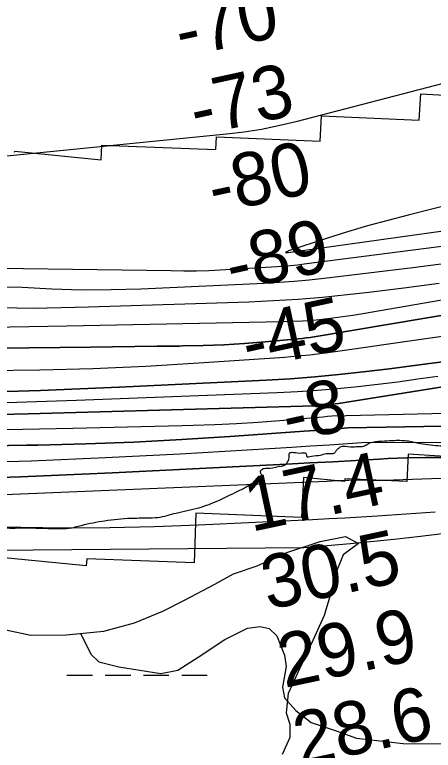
# Model space of a CAD drawing. Extents: x 3297772 to 3335630, y 634068 to 659439.
# Drawn here: x 3327309 to 3327833, y 645151 to 646073 of the extents above; entities that cross this region are included whole.
import ezdxf

# ---------------------------------------------------------------- set-up
doc = ezdxf.new("R2010")
doc.units = 0
for name, color, linetype in [('V-RIVR-EDGE', 7, 'Continuous'), ('V-RIVR-RANG', 7, 'Continuous'), ('V-RRAP-RVMT', 7, 'Continuous'), ('V-SITE-VEGE', 7, 'Continuous'), ('V-TOPO-DPTH', 7, 'Continuous'), ('V-TOPO-MAJR', 7, 'Continuous'), ('V-TOPO-MINR', 7, 'Continuous'), ('V-TOPO-WATR', 7, 'Continuous'), ('V-WETL-SWMP', 7, 'Continuous')]:
    doc.layers.add(name, color=color, linetype=linetype)

msp = doc.modelspace()

# ---------------------------------------------------------------- linework, layer by layer
at = {"layer": 'V-RIVR-EDGE'}
msp.add_spline([(3325196.76, 645366.57), (3325219.07, 645371.99), (3325232.62, 645380.37), (3325238.11, 645381.45), (3325244.69, 645381.43), (3325256.03, 645384.7), (3325270.28, 645383.93), (3325278.69, 645383.91), (3325292.94, 645383.87), (3325303.18, 645385.68), (3325337.93, 645393.27), (3325341.96, 645396.18), (3325345.26, 645400.19), (3325350.02, 645402.74), (3325363.55, 645407.09), (3325383.3, 645410.34), (3325403.77, 645410.65), (3325424.61, 645412.06), (3325447.65, 645414.56), (3325474.71, 645418.52), (3325488.24, 645421.04), (3325503.6, 645423.2), (3325524.43, 645423.51), (3325540.88, 645421.28), (3325546.37, 645422.36), (3325555.87, 645423.43), (3325573.43, 645427.41), (3325598.29, 645430.64), (3325642.54, 645437.11), (3325676.18, 645439.95), (3325709.08, 645440.6), (3325736.86, 645438.7), (3325745.63, 645439.05), (3325778.18, 645445.91), (3325790.25, 645447.71), (3325816.2, 645448.01), (3325841.42, 645446.85), (3325861.17, 645447.9), (3325877.99, 645450.78), (3325891.88, 645451.48), (3325905.04, 645450.72), (3325915.64, 645449.96), (3325925.51, 645449.94), (3325931.73, 645453.58), (3325946.36, 645457.2), (3325975.98, 645462.24), (3326020.59, 645466.52), (3326051.66, 645467.17), (3326078.35, 645468.93), (3326092.26, 645474.75), (3326108.35, 645477.63), (3326121.15, 645479.43), (3326134.67, 645479.39), (3326146.37, 645479), (3326156.98, 645483.73), (3326173.06, 645481.86), (3326186.58, 645479.63), (3326209.25, 645482.5), (3326231.92, 645484.27), (3326245.82, 645486.8), (3326251.3, 645487.51), (3326255.69, 645487.5), (3326266.65, 645484.55), (3326272.13, 645484.9), (3326286.76, 645485.6), (3326304.31, 645487.02), (3326331.71, 645482.93), (3326352.19, 645483.24), (3326375.22, 645483.92), (3326399.71, 645484.95), (3326430.42, 645487.07), (3326472.11, 645494.64), (3326504.66, 645500.78), (3326533.19, 645508.02), (3326555.14, 645512.72), (3326569.77, 645515.24), (3326590.6, 645516.28), (3326611.44, 645516.96), (3326626.07, 645517.29), (3326648.74, 645520.16), (3326682.73, 645518.61), (3326701.37, 645519.67), (3326720.39, 645522.91), (3326726.24, 645522.89), (3326745.6, 645516.63), (3326754.37, 645517.71), (3326767.18, 645522.43), (3326775.22, 645522.41), (3326789.47, 645520.91), (3326806.64, 645515.75), (3326817.97, 645513.16), (3326835.51, 645512.75), (3326847.57, 645511.63), (3326853.78, 645509.42), (3326864.75, 645508.29), (3326886.31, 645508.61), (3326901.66, 645506.01), (3326929.42, 645497.17), (3326947.69, 645495.3), (3326969.62, 645490.49), (3326983.5, 645489.36), (3327007.99, 645487.47), (3327024.79, 645482.31), (3327048.53, 645473.84), (3327083.59, 645460.96), (3327102.59, 645457.26), (3327123.05, 645450.63), (3327142.04, 645445.1), (3327153.38, 645445.8), (3327176.02, 645437.34), (3327197.58, 645434.36), (3327219.15, 645434.31), (3327235.22, 645431.71), (3327254.59, 645429.83), (3327257.15, 645427.63), (3327254.58, 645423.62), (3327249.09, 645419.98), (3327247.62, 645417.42), (3327250.17, 645413.76), (3327256.38, 645412.65), (3327262.23, 645412.63), (3327269.91, 645413.71), (3327273.57, 645415.53), (3327277.23, 645418.81), (3327282.37, 645427.57), (3327290.05, 645429.75), (3327306.5, 645429.71), (3327316.74, 645430.05), (3327337.57, 645429.63), (3327362.43, 645429.2), (3327376.69, 645429.53), (3327392.41, 645433.15), (3327421.31, 645438.93), (3327454.21, 645442.13), (3327473.95, 645442.45), (3327488.21, 645443.15), (3327510.89, 645448.57), (3327539.05, 645455.08), (3327565.4, 645464.89), (3327591.75, 645477.62), (3327596.87, 645480.16), (3327603.46, 645484.17), (3327608.95, 645487.08), (3327619.57, 645492.9), (3327619.57, 645494.37), (3327617.02, 645498.39), (3327616.66, 645500.59), (3327617.4, 645502.05), (3327621.42, 645504.6), (3327628.37, 645504.94), (3327642.63, 645507.47), (3327647.02, 645508.55), (3327651.79, 645514.39), (3327652.52, 645515.85), (3327653.64, 645524.26), (3327655.1, 645524.62), (3327658.03, 645524.61), (3327668.26, 645523.85), (3327673.01, 645523.84), (3327674.11, 645522.74), (3327674.47, 645519.82), (3327680.68, 645519.8), (3327691.65, 645521.24), (3327699.33, 645523.05), (3327707.74, 645523.39), (3327709.93, 645524.12), (3327712.14, 645527.4), (3327715.43, 645530.32), (3327716.9, 645531.41), (3327729.69, 645531.38), (3327739.2, 645532.09), (3327745.78, 645532.44), (3327750.9, 645534.98), (3327757.12, 645537.53), (3327772.48, 645538.95), (3327784.91, 645539.65), (3327802.45, 645538.88), (3327817.07, 645535.91), (3327829.86, 645534.06), (3327842.28, 645532.93), (3327856.91, 645533.26), (3327866.41, 645534.33), (3327870.44, 645536.51), (3327879.22, 645537.22), (3327886.16, 645537.57), (3327892.01, 645538.65), (3327898.23, 645538.64), (3327904.08, 645538.62), (3327915.77, 645534.94), (3327925.63, 645534.55), (3327947.21, 645537.06), (3327969.14, 645537.73), (3327991.81, 645538.04), (3328022.88, 645537.6), (3328037.49, 645535.74), (3328060.16, 645536.04), (3328088.31, 645536.34), (3328117.55, 645537.37), (3328121.94, 645535.89), (3328132.53, 645533.67), (3328150.81, 645535.09), (3328167.63, 645534.32), (3328186.64, 645536.83), (3328199.44, 645540.09), (3328214.44, 645541.88), (3328232.35, 645542.93), (3328250.99, 645542.15), (3328289.37, 645541.69), (3328309.85, 645543.84), (3328325.21, 645547.82), (3328337.3, 645556.56), (3328349.76, 645568.96), (3328357.82, 645579.54), (3328362.59, 645586.47), (3328365.52, 645587.93), (3328369.54, 645588.28), (3328387.82, 645586.41), (3328406.82, 645583.07), (3328410.84, 645583.06), (3328415.59, 645584.15), (3328422.17, 645584.13), (3328433.86, 645580.81), (3328450.66, 645574.56), (3328468.55, 645563.91), (3328480.23, 645556.57), (3328490.82, 645555.09), (3328505.81, 645553.22), (3328518.95, 645546.97), (3328533.19, 645539.99), (3328537.57, 645539.25), (3328541.23, 645539.97), (3328548.17, 645537.4), (3328551.82, 645534.1), (3328555.84, 645532.63), (3328561.68, 645532.25), (3328569.73, 645533.69), (3328596.79, 645537.64), (3328623.85, 645539.77), (3328643.95, 645540.45), (3328661.5, 645541.87), (3328682.34, 645542.18), (3328707.93, 645541.39), (3328751.8, 645544.94), (3328776.29, 645544.14), (3328800.41, 645542.99), (3328822.34, 645540.74), (3328852.31, 645540.3), (3328872.42, 645539.52), (3328885.21, 645538.03), (3328904.21, 645535.05), (3328911.52, 645534.67), (3328920.29, 645534.65), (3328935.65, 645535.34), (3328949.9, 645535.67), (3328970.74, 645535.26), (3328996.69, 645533), (3329015.69, 645532.22), (3329030.32, 645534.01), (3329055.19, 645539.07), (3329082.26, 645548.5), (3329110.8, 645559.4), (3329140.81, 645572.85), (3329150.69, 645574.29), (3329156.53, 645572.81), (3329161.99, 645564.03), (3329167.83, 645559.26), (3329176.96, 645555.22), (3329189.39, 645555.19), (3329198.9, 645558.09), (3329204.02, 645560.27), (3329207.32, 645563.91), (3329210.26, 645571.22), (3329213.2, 645575.96), (3329221.99, 645583.25), (3329230.78, 645588.35), (3329243.95, 645594.9), (3329264.07, 645601.43), (3329299.92, 645609.38), (3329325.51, 645612.24), (3329356.22, 645614.36), (3329383.65, 645617.58), (3329433.01, 645624.4), (3329465.56, 645631.27), (3329478.74, 645637.45), (3329492.65, 645643.26), (3329501.79, 645643.97), (3329512.02, 645644.68), (3329517.87, 645644.66), (3329517.87, 645642.84), (3329522.24, 645637.71), (3329527.36, 645636.6), (3329531.01, 645636.95), (3329539.79, 645639.13), (3329550.03, 645641.66), (3329558.44, 645641.64), (3329571.59, 645637.95), (3329581.45, 645634.27), (3329594.96, 645629.49), (3329608.46, 645619.22), (3329621.6, 645611.14), (3329628.55, 645610.03), (3329633.3, 645610.38), (3329647.95, 645620.58), (3329662.22, 645626.03), (3329671.72, 645627.1), (3329687.81, 645626.33), (3329707.91, 645624.82), (3329744.09, 645622.54), (3329761.64, 645621.76), (3329766.75, 645621.02), (3329774.06, 645620.64), (3329779.18, 645621.35), (3329786.85, 645618.41), (3329792.32, 645614.74), (3329809.5, 645610.68), (3329840.92, 645606.94)], degree=3, dxfattribs=at)
at = {"layer": 'V-RRAP-RVMT'}
for p, q in [((3327815.69, 645941.15), (3327817.77, 645974.23)), ((3327817.77, 645974.23), (3327958.55, 645966.13)), ((3327691.81, 645914.84), (3327693.27, 645946.56)), ((3327693.27, 645946.56), (3327815.69, 645941.15)), ((3327560.7, 645904.5), (3327561.43, 645920.37)), ((3327561.43, 645920.37), (3327691.81, 645914.84)), ((3327417.01, 645891.44), (3327417.81, 645909.69)), ((3327417.81, 645909.69), (3327560.7, 645904.5)), ((3327308.52, 645900.8), (3327308.64, 645902.05)), ((3327308.64, 645902.05), (3327417.01, 645891.44)), ((3327801.82, 645522.17), (3327800.2, 645487.91)), ((3327937.16, 645514.4), (3327801.82, 645522.17)), ((3327670.59, 645493.31), (3327668.41, 645443.07)), ((3327722, 645487.96), (3327670.59, 645493.31)), ((3327722.36, 645491.41), (3327722, 645487.96)), ((3327800.2, 645487.91), (3327722.36, 645491.41)), ((3327535.85, 645448.6), (3327533.66, 645386.07)), ((3327668.41, 645443.07), (3327535.85, 645448.6)), ((3327398.03, 645382.52), (3327259.58, 645395.96)), ((3327398.88, 645391.03), (3327398.03, 645382.52)), ((3327533.66, 645386.07), (3327398.88, 645391.03))]:
    msp.add_line(p, q, dxfattribs=at)
at = {"layer": 'V-SITE-VEGE'}
msp.add_lwpolyline([(3327297.44, 645302.08), (3327328.77, 645295.47), (3327373.27, 645295.8), (3327420.48, 645300.39), (3327458.8, 645310.8), (3327494.41, 645325.46), (3327521.52, 645339.35), (3327559.46, 645359.43), (3327583.08, 645372.17), (3327612.49, 645382.58), (3327649.66, 645399.18), (3327691.46, 645413.06), (3327723.2, 645419.22), (3327739.5, 645410.57), (3327720.43, 645396.26), (3327710.9, 645372.41), (3327708.51, 645355.71), (3327703.74, 645343.78), (3327696.59, 645319.93), (3327682.29, 645288.92), (3327665.6, 645253.15), (3327651.3, 645222.14), (3327648.91, 645198.29), (3327653.68, 645183.98), (3327653.68, 645167.28), (3327644.15, 645145.81)], dxfattribs=at)
at = {"layer": 'V-TOPO-DPTH'}
for points in [[(3328198.59, 645755.91), (3327684.12, 645669.54), (3327679.13, 645668.76), (3327674.14, 645668.06), (3327669.13, 645667.48), (3327664.11, 645666.97), (3327622.45, 645663.25), (3327596.57, 645661.25), (3327570.68, 645659.64), (3327544.75, 645658.62), (3327518.81, 645658.01), (3327514.96, 645657.96), (3327487.08, 645657.63), (3327459.2, 645657.3), (3327431.32, 645656.97), (3327403.44, 645656.64), (3327210.13, 645654.4), (3327104.28, 645653.12), (3326998.43, 645651.75), (3326892.58, 645650.28), (3326786.73, 645648.72), (3326647.86, 645646.61)], [(3328198.59, 645755.91), (3327684.12, 645669.54), (3327679.13, 645668.76), (3327674.14, 645668.06), (3327669.13, 645667.48), (3327664.11, 645666.97), (3327622.45, 645663.25), (3327596.57, 645661.25), (3327570.68, 645659.64), (3327544.75, 645658.62), (3327518.81, 645658.01), (3327514.96, 645657.96), (3327487.08, 645657.63), (3327459.2, 645657.3), (3327431.32, 645656.97), (3327403.44, 645656.64), (3327210.13, 645654.4), (3327104.28, 645653.12), (3326998.43, 645651.75), (3326892.58, 645650.28), (3326786.73, 645648.72), (3326647.86, 645646.61)], [(3326717.66, 645622.15), (3326787.87, 645623.57), (3326858.09, 645624.73), (3326928.31, 645625.5), (3326998.54, 645626.01), (3327007.12, 645626.05), (3327073.69, 645626.34), (3327140.25, 645626.63), (3327206.82, 645626.9), (3327273.39, 645627.16), (3327339.93, 645628.06), (3327406.44, 645629.83), (3327472.91, 645632.88), (3327539.34, 645636.79), (3327646.77, 645644.16), (3327662.76, 645645.44), (3327678.73, 645646.96), (3327694.65, 645648.84), (3327710.55, 645650.96), (3327929.11, 645682.62)], [(3326717.66, 645622.15), (3326787.87, 645623.57), (3326858.09, 645624.73), (3326928.31, 645625.5), (3326998.54, 645626.01), (3327007.12, 645626.05), (3327073.69, 645626.34), (3327140.25, 645626.63), (3327206.82, 645626.9), (3327273.39, 645627.16), (3327339.93, 645628.06), (3327406.44, 645629.83), (3327472.91, 645632.88), (3327539.34, 645636.79), (3327646.77, 645644.16), (3327662.76, 645645.44), (3327678.73, 645646.96), (3327694.65, 645648.84), (3327710.55, 645650.96), (3327929.11, 645682.62)], [(3328279.42, 645676.32), (3327714.71, 645586), (3327711, 645585.44), (3327707.28, 645584.93), (3327703.55, 645584.48), (3327699.82, 645584.08), (3327696.08, 645583.75), (3327692.34, 645583.47), (3327688.59, 645583.27), (3327684.84, 645583.13), (3327325.61, 645572.79), (3327201.58, 645569.87), (3327077.54, 645567.81), (3326953.48, 645567.05), (3326829.41, 645567.16), (3326609.21, 645568.5)], [(3326609.21, 645568.5), (3326829.41, 645567.16), (3326953.48, 645567.05), (3327077.54, 645567.81), (3327201.58, 645569.87), (3327325.61, 645572.79), (3327684.84, 645583.13), (3327688.59, 645583.27), (3327692.34, 645583.47), (3327696.08, 645583.75), (3327699.82, 645584.08), (3327703.55, 645584.48), (3327707.28, 645584.93), (3327711, 645585.44), (3327714.71, 645586), (3328279.42, 645676.32)], [(3326750.06, 645598.6), (3326782.39, 645598.64), (3326814.71, 645598.55), (3326847.04, 645598.45), (3326879.36, 645598.32), (3326911.69, 645598.19), (3327044.68, 645597.6), (3327143.48, 645597.94), (3327242.26, 645599.32), (3327341, 645602.28), (3327439.72, 645606.27), (3327623.97, 645615.2), (3327654.39, 645617), (3327684.76, 645619.25), (3327715.09, 645622.16), (3327745.37, 645625.51), (3327778.48, 645629.54), (3327825.26, 645635.42), (3327872.01, 645641.55)], [(3327872.01, 645641.55), (3327825.26, 645635.42), (3327778.48, 645629.54), (3327745.37, 645625.51), (3327715.09, 645622.16), (3327684.76, 645619.25), (3327654.39, 645617), (3327623.97, 645615.2), (3327439.72, 645606.27), (3327341, 645602.28), (3327242.26, 645599.32), (3327143.48, 645597.94), (3327044.68, 645597.6), (3326911.69, 645598.19), (3326879.36, 645598.32), (3326847.04, 645598.45), (3326814.71, 645598.55), (3326782.39, 645598.64), (3326750.06, 645598.6)], [(3328179.47, 645563.23), (3327726.25, 645555.39), (3327712.55, 645554.27), (3327698.85, 645553.18), (3327685.14, 645552.14), (3327671.44, 645551.13), (3327578.46, 645544.47), (3327518.24, 645540.64), (3327458, 645537.48), (3327397.7, 645535.29), (3327337.38, 645533.76), (3327323.16, 645533.52), (3327255.7, 645532.4), (3327188.24, 645531.32), (3327120.78, 645530.32), (3327053.32, 645529.36), (3327016.04, 645528.85), (3326944.03, 645527.72), (3326872.02, 645526.39), (3326800.03, 645524.77), (3326728.03, 645522.94)], [(3326728.03, 645522.94), (3326800.03, 645524.77), (3326872.02, 645526.39), (3326944.03, 645527.72), (3327016.04, 645528.85), (3327053.32, 645529.36), (3327120.78, 645530.32), (3327188.24, 645531.32), (3327255.7, 645532.4), (3327323.16, 645533.52), (3327337.38, 645533.76), (3327397.7, 645535.29), (3327458, 645537.48), (3327518.24, 645540.64), (3327578.46, 645544.47), (3327671.44, 645551.13), (3327685.14, 645552.14), (3327698.85, 645553.18), (3327712.55, 645554.27), (3327726.25, 645555.39), (3328179.47, 645563.23)], [(3327846.88, 645518.11), (3327823.53, 645518.34), (3327800.19, 645517.82), (3327776.85, 645516.82), (3327765.53, 645516.15), (3327736.54, 645514.48), (3327707.53, 645512.86), (3327678.53, 645511.32), (3327649.52, 645509.83), (3327431.22, 645498.95), (3327315.79, 645494.07), (3327200.33, 645490.36), (3327084.84, 645488.39), (3326969.31, 645487.59), (3326775.01, 645487.7), (3326756.61, 645487.71)]]:
    msp.add_lwpolyline(points, dxfattribs=at)
at = {"layer": 'V-TOPO-MAJR'}
for points in [[(3328247.45, 645785.15), (3327744.92, 645698.33), (3327732.44, 645696.3), (3327719.94, 645694.42), (3327707.4, 645692.79), (3327694.85, 645691.32), (3327682.26, 645690.13), (3327669.67, 645689.16), (3327657.05, 645688.52), (3327644.41, 645688.11), (3327373.91, 645682.66), (3327254.58, 645680.72), (3327135.25, 645679.41), (3327015.91, 645679.04), (3326896.56, 645679.29), (3326677.05, 645680.61)], [(3325791.53, 645324.4), (3326162.63, 645362), (3326233.92, 645368.79), (3326305.25, 645375.02), (3326376.65, 645380.4), (3326448.09, 645385.21), (3326570.3, 645392.71), (3326580.67, 645393.3), (3326591.06, 645393.83), (3326601.44, 645394.27), (3326611.83, 645394.64), (3326676.89, 645396.66), (3326700.9, 645397.19), (3326724.92, 645397.44), (3326748.93, 645397.26), (3327671.04, 645405.43), (3327700.32, 645407.88), (3327729.58, 645410.5), (3327758.82, 645413.34), (3327788.05, 645416.34), (3327817.26, 645419.53), (3328312.72, 645480.27)]]:
    msp.add_lwpolyline(points, dxfattribs=at)
at = {"layer": 'V-TOPO-MINR'}
for points in [[(3328021.09, 646032.42), (3327661.02, 645938.92), (3327639.54, 645933.87), (3327617.94, 645929.49), (3327596.16, 645926.11), (3327574.26, 645923.4), (3327285.74, 645894.52), (3327204.27, 645888.2), (3327122.74, 645884.31), (3327041.13, 645884.07), (3326959.44, 645886.26), (3326832.02, 645892.54), (3326814.02, 645893.63), (3326796.05, 645894.98), (3326778.11, 645896.73), (3326760.19, 645898.74)], [(3328177.24, 645917.08), (3327801.87, 645822.2), (3327776.43, 645815.5), (3327751.08, 645808.47), (3327725.89, 645800.94), (3327700.78, 645793.07), (3327652.02, 645777.25), (3327651.38, 645777.02), (3327648.4, 645775.46), (3327648.34, 645775.37), (3327648.33, 645775.29), (3327648.38, 645775.22), (3327648.47, 645775.16), (3327648.71, 645775.14), (3327649.43, 645775.15), (3327651.06, 645775.27), (3327651.18, 645775.28), (3327651.3, 645775.3), (3328135.77, 645842.73)], [(3326577.87, 645765.29), (3327504.8, 645752.73), (3327520.56, 645752.05), (3327536.34, 645752.11), (3327552.13, 645752.67), (3327637.49, 645757.72), (3327646.05, 645758.31), (3327654.59, 645759.02), (3327663.12, 645759.91), (3327671.63, 645760.92), (3327974.35, 645799.91)], [(3325814.39, 645749.8), (3326072.71, 645741.63), (3326155.7, 645739.72), (3326238.69, 645738.76), (3326321.68, 645739.22), (3326404.67, 645740.63), (3326542.93, 645744.16), (3326556.8, 645744.56), (3326570.66, 645745), (3326584.53, 645745.53), (3326598.39, 645746.11), (3327317.76, 645731.54), (3327354.94, 645729.65), (3327392.13, 645728.59), (3327429.34, 645728.8), (3327466.56, 645729.85), (3327621.21, 645736.85), (3327640.06, 645737.91), (3327658.9, 645739.25), (3327677.7, 645741.02), (3327696.48, 645743.06), (3327807.66, 645756.42), (3327881.95, 645765.83)], [(3326647.86, 645646.61), (3326786.73, 645648.72), (3326892.58, 645650.28), (3326998.43, 645651.75), (3327104.28, 645653.12), (3327210.13, 645654.4), (3327403.44, 645656.64), (3327431.32, 645656.97), (3327459.2, 645657.3), (3327487.08, 645657.63), (3327514.96, 645657.96), (3327518.81, 645658.01), (3327544.75, 645658.62), (3327570.68, 645659.64), (3327596.57, 645661.25), (3327622.45, 645663.25), (3327664.11, 645666.97), (3327669.13, 645667.48), (3327674.14, 645668.06), (3327679.13, 645668.76), (3327684.12, 645669.54), (3328198.59, 645755.91)], [(3327840.77, 645736.28), (3327796.65, 645730.45), (3327752.47, 645725.09), (3327725.41, 645722.03), (3327694.68, 645718.93), (3327663.92, 645716.32), (3327633.1, 645714.46), (3327602.24, 645713.09), (3327401.01, 645706.6), (3327332.35, 645705.1), (3326626.36, 645719.04), (3326598.91, 645718.43), (3326571.47, 645717.87), (3326544.02, 645717.4), (3326516.57, 645716.99), (3326123.09, 645711.67), (3326060.18, 645711.19), (3325997.27, 645711.2), (3325934.37, 645711.95), (3325871.47, 645713.19), (3325779.55, 645715.54)], [(3326717.66, 645622.15), (3326787.87, 645623.57), (3326858.09, 645624.73), (3326928.31, 645625.5), (3326998.54, 645626.01), (3327007.12, 645626.05), (3327073.69, 645626.34), (3327140.25, 645626.63), (3327206.82, 645626.9), (3327273.39, 645627.16), (3327339.93, 645628.06), (3327406.44, 645629.83), (3327472.91, 645632.88), (3327539.34, 645636.79), (3327646.77, 645644.16), (3327662.76, 645645.44), (3327678.73, 645646.96), (3327694.65, 645648.84), (3327710.55, 645650.96), (3327929.11, 645682.62)], [(3326609.21, 645568.5), (3326829.41, 645567.16), (3326953.48, 645567.05), (3327077.54, 645567.81), (3327201.58, 645569.87), (3327325.61, 645572.79), (3327684.84, 645583.13), (3327688.59, 645583.27), (3327692.34, 645583.47), (3327696.08, 645583.75), (3327699.82, 645584.08), (3327703.55, 645584.48), (3327707.28, 645584.93), (3327711, 645585.44), (3327714.71, 645586), (3328279.42, 645676.32)], [(3326750.06, 645598.6), (3326782.39, 645598.64), (3326814.71, 645598.55), (3326847.04, 645598.45), (3326879.36, 645598.32), (3326911.69, 645598.19), (3327044.68, 645597.6), (3327143.48, 645597.94), (3327242.26, 645599.32), (3327341, 645602.28), (3327439.72, 645606.27), (3327623.97, 645615.2), (3327654.39, 645617), (3327684.76, 645619.25), (3327715.09, 645622.16), (3327745.37, 645625.51), (3327778.48, 645629.54), (3327825.26, 645635.42), (3327872.01, 645641.55)], [(3326738.75, 645584.89), (3326934.29, 645583.19), (3327047.24, 645583.01), (3327160.18, 645583.9), (3327273.1, 645586.38), (3327386, 645589.92), (3327637.88, 645599.61), (3327663.13, 645600.86), (3327688.36, 645602.46), (3327713.55, 645604.6), (3327738.71, 645607.1), (3327763.83, 645610.03), (3327788.92, 645613.18), (3327813.96, 645616.66), (3327838.98, 645620.35)], [(3326645.78, 645537.39), (3326779.42, 645541.06), (3326877.58, 645543.66), (3326975.74, 645546.14), (3327073.91, 645548.43), (3327172.07, 645550.6), (3327381.53, 645555.04), (3327415.76, 645555.79), (3327449.99, 645556.57), (3327484.22, 645557.4), (3327518.44, 645558.26), (3327532.48, 645558.62), (3327559.68, 645559.57), (3327586.85, 645560.83), (3327614.01, 645562.56), (3327641.14, 645564.62), (3327684.41, 645568.27), (3327689.9, 645568.75), (3327695.38, 645569.26), (3327700.86, 645569.8), (3327706.34, 645570.37), (3328332.5, 645585.07)], [(3326768.32, 645506.85), (3326814.16, 645507.48), (3326860, 645507.92), (3326860.82, 645507.92), (3326907.07, 645508.23), (3326953.33, 645508.55), (3326999.59, 645508.91), (3327045.84, 645509.28), (3327142.04, 645510.08), (3327235.6, 645511.59), (3327329.14, 645514.06), (3327422.63, 645517.99), (3327516.08, 645522.89), (3327656.14, 645531.32), (3327679.53, 645532.77), (3327702.93, 645534.26), (3327726.31, 645535.83), (3327749.7, 645537.45), (3328175.02, 645536.38)], [(3326756.61, 645487.71), (3326775.01, 645487.7), (3326969.31, 645487.59), (3327084.84, 645488.39), (3327200.33, 645490.36), (3327315.79, 645494.07), (3327431.22, 645498.95), (3327649.52, 645509.83), (3327678.53, 645511.32), (3327707.53, 645512.86), (3327736.54, 645514.48), (3327765.53, 645516.15), (3327776.85, 645516.82), (3327800.19, 645517.82), (3327823.53, 645518.34), (3327846.88, 645518.11)], [(3326671.29, 645457.81), (3326826.96, 645459.57), (3326946.66, 645461.47), (3327066.34, 645464.09), (3327186, 645467.81), (3327305.63, 645472.24), (3327699.82, 645488.66), (3327706.21, 645488.93), (3327712.61, 645489.22), (3327719, 645489.51), (3327725.39, 645489.81), (3327727.08, 645489.89), (3327732.63, 645490.09), (3327738.18, 645490.21), (3327743.73, 645490.19), (3327749.28, 645490.08), (3327754.83, 645489.92), (3327760.38, 645489.79), (3327765.93, 645489.68), (3327771.48, 645489.6), (3328309.68, 645508.58)], [(3326745.63, 645426.01), (3326822.11, 645428.11), (3326898.6, 645429.82), (3326975.1, 645430.97), (3327051.61, 645431.74), (3327093.06, 645432.01), (3327148.85, 645432.16), (3327204.64, 645432.03), (3327260.43, 645431.5), (3327316.21, 645430.68), (3327371.98, 645430.21), (3327427.75, 645430.46), (3327483.5, 645431.81), (3327539.24, 645433.87), (3327682.06, 645440.57), (3327702.35, 645441.58), (3327722.65, 645442.68), (3327742.93, 645443.89), (3327763.21, 645445.19), (3327835.74, 645450.05)]]:
    msp.add_lwpolyline(points, dxfattribs=at)
at = {"layer": 'V-TOPO-WATR'}
msp.add_lwpolyline([(3326728.03, 645522.94), (3326800.03, 645524.77), (3326872.02, 645526.39), (3326944.03, 645527.72), (3327016.04, 645528.85), (3327053.32, 645529.36), (3327120.78, 645530.32), (3327188.24, 645531.32), (3327255.7, 645532.4), (3327323.16, 645533.52), (3327337.38, 645533.76), (3327397.7, 645535.29), (3327458, 645537.48), (3327518.24, 645540.64), (3327578.46, 645544.47), (3327671.44, 645551.13), (3327685.14, 645552.14), (3327698.85, 645553.18), (3327712.55, 645554.27), (3327726.25, 645555.39), (3328179.47, 645563.23)], dxfattribs=at)
at = {"layer": 'V-WETL-SWMP'}
for p, q in [((3327374.03, 645245.23), (3327406.03, 645245.23)), ((3327422.03, 645245.23), (3327454.03, 645245.23)), ((3327470.03, 645245.23), (3327502.03, 645245.23)), ((3327518.03, 645245.23), (3327550.03, 645245.23))]:
    msp.add_line(p, q, dxfattribs=at)
msp.add_lwpolyline([(3327297.44, 645302.08), (3327328.77, 645295.47), (3327373.27, 645295.8), (3327391.2, 645297.55), (3327404.35, 645271.36), (3327414.08, 645262), (3327439, 645255.74), (3327491.97, 645247.5), (3327513.01, 645251.76), (3327538.74, 645267.7), (3327572.26, 645289.86), (3327600.33, 645304.24), (3327616.3, 645306.17), (3327627.59, 645303.82), (3327637.32, 645294.46), (3327641.98, 645282.77), (3327647.03, 645270.3), (3327648.96, 645256.27), (3327644.26, 645230.18), (3327646.97, 645216.93), (3327660.98, 645200.95), (3327680.44, 645186.12), (3327711.59, 645175.57), (3327737.29, 645166.19), (3327795.71, 645159.5), (3327858.43, 645159.04)], dxfattribs=at)

# ---------------------------------------------------------------- texts
at = {"layer": 'V-RIVR-RANG'}
for s, rotation, p in [('-70', 12.28314, (3327517.2, 646019.11)), ('-73', 12.28314, (3327535.91, 645920.84)), ('-80', 12.28314, (3327558.75, 645823.47)), ('-89', 12.28314, (3327580.81, 645725.93)), ('-45', 12.28314, (3327601.07, 645628)), ('-8', 12.28314, (3327651.49, 645536.63)), ('17.4', 11.99833, (3327604.96, 645424.76)), ('30.5', 11.99833, (3327626, 645327)), ('29.9', 11.99833, (3327646.77, 645229.18)), ('28.6', 11.99833, (3327666.26, 645131.09))]:
    msp.add_text(s, height=67, rotation=rotation, dxfattribs=at).set_placement(p)

doc.saveas('drawing.dxf')
